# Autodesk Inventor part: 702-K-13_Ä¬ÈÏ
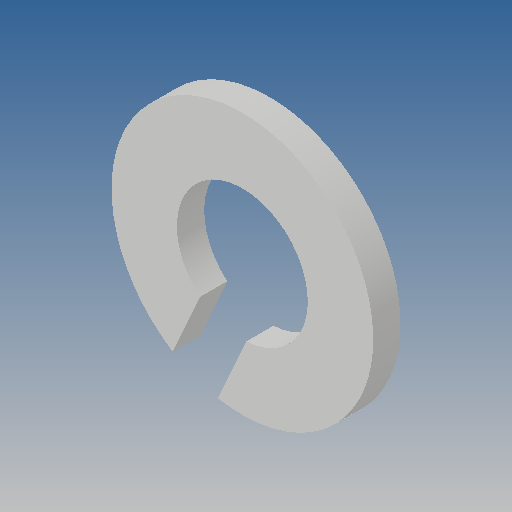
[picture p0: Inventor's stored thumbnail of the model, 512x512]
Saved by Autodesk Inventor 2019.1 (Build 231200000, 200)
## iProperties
Created: 2010-06
Part Number: 702-K-13_Ä¬ÈÏ
Material: Ogólny
Document SubType Name: Modeling
Designer: CADENGINEERING4
Density: 1 g/cm^3
Appearance: Domyślna
Author: CADENGINEERING4
Revision Number: ÈÎºÎ
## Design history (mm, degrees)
feature "NONE"
node "Bryła1"
